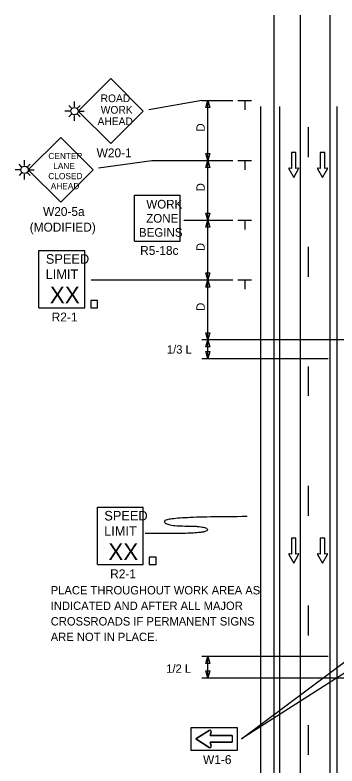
# Model space of a CAD drawing. Extents: x 16748 to 18475, y 7008 to 8262.
# Drawn here: x 16772 to 17041, y 7634 to 8262 of the extents above; entities that cross this region are included whole.
import ezdxf

# ---------------------------------------------------------------- set-up
doc = ezdxf.new("R2010")
doc.units = 0
for name, color, linetype in [('ALI_LEGAL_EX', 7, 'Continuous'), ('MT_SCRATCH_LEVEL_E', 7, 'Continuous'), ('PAVT_EDGE_EX', 7, 'Continuous'), ('TRAFFIC_SIGNS_PR', 7, 'Continuous'), ('TYPICAL_TEXT_DIMEN_PR', 7, 'Continuous')]:
    doc.layers.add(name, color=color, linetype=linetype)

msp = doc.modelspace()

# ---------------------------------------------------------------- linework, layer by layer
at = {"layer": 'ALI_LEGAL_EX'}
for points in [[(17017.08, 8168.47), (17017.08, 8143.47)], [(17017.08, 8068.47), (17017.08, 8043.47)], [(17017.08, 7968.47), (17017.08, 7943.81)], [(17017.08, 7868.47), (17017.08, 7843.47)], [(17017.08, 7768.47), (17017.08, 7743.47)], [(17017.08, 7668.47), (17017.08, 7643.47)]]:
    msp.add_lwpolyline(points, dxfattribs=at)
at = {"layer": 'MT_SCRATCH_LEVEL_E'}
for p, q in [((17006.75, 8147.27), (17003.01, 8147.27)), ((17003.01, 8147.27), (17003.01, 8134.01)), ((17006.75, 8147.27), (17003.01, 8147.27)), ((17003.01, 8147.27), (17003.01, 8134.01)), ((17006.75, 8134.01), (17006.75, 8147.27)), ((17006.75, 8134.01), (17006.75, 8147.27)), ((17030.82, 8147.27), (17027.08, 8147.27)), ((17027.08, 8147.27), (17027.08, 8134.01)), ((17030.82, 8147.27), (17027.08, 8147.27)), ((17027.08, 8147.27), (17027.08, 8134.01)), ((17030.82, 8134.01), (17030.82, 8147.27)), ((17030.82, 8134.01), (17030.82, 8147.27)), ((17000.75, 8133.64), (17004.9, 8126.4)), ((17000.75, 8133.64), (17004.9, 8126.4)), ((17003.01, 8134.01), (17001.23, 8134.32)), ((17003.01, 8134.01), (17001.23, 8134.32)), ((17004.9, 8126.4), (17009.01, 8133.64)), ((17004.9, 8126.4), (17009.01, 8133.64)), ((17008.53, 8134.32), (17006.75, 8134.01)), ((17008.53, 8134.32), (17006.75, 8134.01)), ((17024.82, 8133.64), (17028.97, 8126.4)), ((17024.82, 8133.64), (17028.97, 8126.4)), ((17027.08, 8134.01), (17025.3, 8134.32)), ((17027.08, 8134.01), (17025.3, 8134.32)), ((17028.97, 8126.4), (17033.08, 8133.64)), ((17028.97, 8126.4), (17033.08, 8133.64)), ((17032.6, 8134.32), (17030.82, 8134.01)), ((17032.6, 8134.32), (17030.82, 8134.01)), ((17006.75, 7824.7), (17003.01, 7824.7)), ((17003.01, 7824.7), (17003.01, 7811.45)), ((17006.75, 7824.7), (17003.01, 7824.7)), ((17003.01, 7824.7), (17003.01, 7811.45)), ((17006.75, 7811.45), (17006.75, 7824.7)), ((17006.75, 7811.45), (17006.75, 7824.7)), ((17030.82, 7824.7), (17027.08, 7824.7)), ((17027.08, 7824.7), (17027.08, 7811.45)), ((17030.82, 7824.7), (17027.08, 7824.7)), ((17027.08, 7824.7), (17027.08, 7811.45)), ((17030.82, 7811.45), (17030.82, 7824.7)), ((17030.82, 7811.45), (17030.82, 7824.7)), ((17000.75, 7811.08), (17004.9, 7803.84)), ((17000.75, 7811.08), (17004.9, 7803.84)), ((17003.01, 7811.45), (17001.23, 7811.76)), ((17003.01, 7811.45), (17001.23, 7811.76)), ((17004.9, 7803.84), (17009.01, 7811.08)), ((17004.9, 7803.84), (17009.01, 7811.08)), ((17008.53, 7811.76), (17006.75, 7811.45)), ((17008.53, 7811.76), (17006.75, 7811.45)), ((17024.82, 7811.08), (17028.97, 7803.84)), ((17024.82, 7811.08), (17028.97, 7803.84)), ((17027.08, 7811.45), (17025.3, 7811.76)), ((17027.08, 7811.45), (17025.3, 7811.76)), ((17028.97, 7803.84), (17033.08, 7811.08)), ((17028.97, 7803.84), (17033.08, 7811.08)), ((17032.6, 7811.76), (17030.82, 7811.45)), ((17032.6, 7811.76), (17030.82, 7811.45))]:
    msp.add_line(p, q, dxfattribs=at)
for centre, start, end in [((17001.16, 8133.86), 80.03619, 209.77312), ((17001.16, 8133.86), 80.03619, 209.77312), ((17008.6, 8133.86), 330.42484, 99.96381), ((17008.6, 8133.86), 330.42484, 99.96381), ((17025.23, 8133.86), 80.03619, 209.77312), ((17025.23, 8133.86), 80.03619, 209.77312), ((17032.67, 8133.86), 330.42484, 99.96381), ((17032.67, 8133.86), 330.42484, 99.96381), ((17001.16, 7811.3), 80.03619, 209.77312), ((17001.16, 7811.3), 80.03619, 209.77312), ((17008.6, 7811.3), 330.42484, 99.96381), ((17008.6, 7811.3), 330.42484, 99.96381), ((17025.23, 7811.3), 80.03619, 209.77312), ((17025.23, 7811.3), 80.03619, 209.77312), ((17032.67, 7811.3), 330.42484, 99.96381), ((17032.67, 7811.3), 330.42484, 99.96381)]:
    msp.add_arc(centre, 0.463, start, end, dxfattribs=at)
at = {"layer": 'PAVT_EDGE_EX'}
for p, q in [((16988.15, 8262.34), (16988.15, 7433.15)), ((17010.15, 8262.34), (17010.15, 7433.15)), ((17035.15, 8262.34), (17035.15, 7433.15)), ((16977.08, 8185.96), (16977.08, 7352.54)), ((16993.08, 8185.96), (16993.08, 7352.54)), ((17041.08, 8185.96), (17041.08, 7352.54))]:
    msp.add_line(p, q, dxfattribs=at)
at = {"layer": 'TRAFFIC_SIGNS_PR'}
for p, q in [((16851.77, 8209.12), (16824.59, 8181.93)), ((16878.96, 8181.93), (16851.77, 8209.12)), ((16818.92, 8184.45), (16816.81, 8186.55)), ((16821.43, 8185.49), (16821.43, 8189.99)), ((16823.95, 8184.45), (16826.06, 8186.55)), ((16818.28, 8181.93), (16813.44, 8181.93)), ((16818.92, 8179.42), (16816.81, 8177.31)), ((16821.43, 8173.97), (16821.43, 8178.38)), ((16823.95, 8179.42), (16826.05, 8177.31)), ((16824.59, 8181.93), (16851.77, 8154.75)), ((16824.59, 8181.93), (16829.47, 8181.93)), ((16851.77, 8154.75), (16878.96, 8181.93)), ((16809.95, 8160), (16782.8, 8132.84)), ((16837.1, 8132.84), (16809.95, 8160)), ((16779.65, 8136.4), (16779.65, 8140.9)), ((16777.13, 8135.36), (16775.02, 8137.46)), ((16782.16, 8135.36), (16784.27, 8137.46)), ((16776.49, 8132.84), (16771.65, 8132.84)), ((16777.13, 8130.33), (16775.02, 8128.22)), ((16779.65, 8124.88), (16779.65, 8129.29)), ((16782.16, 8130.33), (16784.27, 8128.22)), ((16782.8, 8132.84), (16787.68, 8132.84)), ((16782.8, 8132.84), (16809.95, 8105.69)), ((16809.95, 8105.69), (16837.1, 8132.84)), ((16871.56, 8073.15), (16871.56, 8111.55)), ((16871.56, 8111.55), (16909.96, 8111.55)), ((16909.96, 8073.15), (16909.96, 8111.55)), ((16871.56, 8073.15), (16909.96, 8073.15)), ((16791.69, 8065.45), (16830.09, 8065.45)), ((16791.69, 8017.45), (16791.69, 8065.45)), ((16830.09, 8017.45), (16830.09, 8065.45)), ((16791.69, 8017.45), (16830.09, 8017.45)), ((16840.63, 7850.72), (16879.03, 7850.72)), ((16840.63, 7802.72), (16840.63, 7850.72)), ((16879.03, 7802.72), (16879.03, 7850.72)), ((16840.63, 7802.72), (16879.03, 7802.72)), ((16934.23, 7664), (16923.07, 7656.9)), ((16935.07, 7659.7), (16935.91, 7662.76)), ((16923.07, 7656.9), (16934.23, 7649.8)), ((16953.47, 7659.7), (16935.07, 7659.7)), ((16953.47, 7659.7), (16953.47, 7654.1)), ((16935.91, 7651.04), (16935.07, 7654.1)), ((16935.07, 7654.1), (16953.47, 7654.1))]:
    msp.add_line(p, q, dxfattribs=at)
for points in [[(16835.11, 8017.45), (16840.7, 8017.45), (16840.7, 8023.62), (16835.11, 8023.62)], [(16884.04, 7802.72), (16889.64, 7802.72), (16889.64, 7808.89), (16884.04, 7808.89)], [(16957.47, 7647.3), (16919.07, 7647.3), (16919.07, 7666.5), (16957.47, 7666.5)]]:
    msp.add_lwpolyline(points, close=True, dxfattribs=at)
for points in [[(16934.23, 7649.8), (16923.07, 7656.9), (16934.23, 7664)], [(16935.91, 7662.76), (16935.07, 7659.7), (16953.47, 7659.7), (16953.47, 7654.1), (16935.07, 7654.1), (16935.91, 7651.04)]]:
    msp.add_lwpolyline(points, dxfattribs=at)
for centre in [(16821.43, 8181.93), (16779.65, 8132.84)]:
    msp.add_circle(centre, 3.15, dxfattribs=at)
for centre, start, end in [((16934.83, 7663.05), 344.67308, 122.46963), ((16934.83, 7663.05), 344.67308, 122.46962), ((16934.83, 7650.74), 237.53038, 15.32692), ((16934.83, 7650.74), 237.53038, 15.32692)]:
    msp.add_arc(centre, 1.12, start, end, dxfattribs=at)
at = {"layer": 'TYPICAL_TEXT_DIMEN_PR'}
for p, q in [((16927.98, 8190.72), (16883.54, 8183.05)), ((16927.98, 8190.72), (16953.98, 8190.72)), ((16931.41, 8184.86), (16932.98, 8190.72)), ((16932.98, 8190.72), (16934.55, 8184.86)), ((16932.98, 8140.72), (16932.98, 8190.72)), ((16958.23, 8190.72), (16969.48, 8190.72)), ((16963.86, 8190.72), (16963.86, 8182.94)), ((16932.98, 8184.86), (16931.41, 8184.86)), ((16934.55, 8184.86), (16932.98, 8184.86)), ((16932.98, 8140.72), (16931.41, 8146.59)), ((16931.41, 8146.59), (16932.98, 8146.59)), ((16932.98, 8146.59), (16934.55, 8146.59)), ((16934.55, 8146.59), (16932.98, 8140.72)), ((16841.56, 8134.45), (16886.16, 8140.72)), ((16886.16, 8140.72), (16953.98, 8140.72)), ((16931.41, 8134.86), (16932.98, 8140.72)), ((16932.98, 8140.72), (16934.55, 8134.86)), ((16932.98, 8090.72), (16932.98, 8140.72)), ((16958.23, 8140.72), (16969.48, 8140.72)), ((16963.86, 8140.72), (16963.86, 8132.94)), ((16932.98, 8134.86), (16931.41, 8134.86)), ((16934.55, 8134.86), (16932.98, 8134.86)), ((16932.98, 8090.72), (16931.41, 8096.59)), ((16931.41, 8096.59), (16932.98, 8096.59)), ((16932.98, 8096.59), (16934.55, 8096.59)), ((16934.55, 8096.59), (16932.98, 8090.72)), ((16912.93, 8090.72), (16953.98, 8090.72)), ((16931.41, 8084.86), (16932.98, 8090.72)), ((16932.98, 8090.72), (16934.55, 8084.86)), ((16932.98, 8040.72), (16932.98, 8090.72)), ((16958.23, 8090.72), (16969.48, 8090.72)), ((16963.86, 8090.72), (16963.86, 8082.94)), ((16932.98, 8084.86), (16931.41, 8084.86)), ((16934.55, 8084.86), (16932.98, 8084.86)), ((16932.98, 8040.72), (16931.41, 8046.59)), ((16931.41, 8046.59), (16932.98, 8046.59)), ((16932.98, 8046.59), (16934.55, 8046.59)), ((16934.55, 8046.59), (16932.98, 8040.72)), ((16835.45, 8040.72), (16953.98, 8040.72)), ((16931.41, 8034.86), (16932.98, 8040.72)), ((16932.98, 7990.72), (16932.98, 8040.72)), ((16932.98, 8040.72), (16934.55, 8034.86)), ((16958.23, 8040.72), (16969.48, 8040.72)), ((16963.86, 8040.72), (16963.86, 8032.94)), ((16932.98, 8034.86), (16931.41, 8034.86)), ((16934.55, 8034.86), (16932.98, 8034.86)), ((16932.98, 7990.72), (16931.41, 7996.59)), ((16931.41, 7996.59), (16932.98, 7996.59)), ((16932.98, 7996.59), (16934.55, 7996.59)), ((16934.55, 7996.59), (16932.98, 7990.72)), ((17058.17, 7990.72), (16927.98, 7990.72)), ((16931.41, 7984.86), (16932.98, 7990.72)), ((16932.98, 7974.96), (16932.98, 7990.72)), ((16932.98, 7990.72), (16934.55, 7984.86)), ((16932.98, 7984.86), (16931.41, 7984.86)), ((16934.55, 7984.86), (16932.98, 7984.86)), ((16932.98, 7974.96), (16931.41, 7980.82)), ((16931.41, 7980.82), (16932.98, 7980.82)), ((16932.98, 7980.82), (16934.55, 7980.82)), ((16934.55, 7980.82), (16932.98, 7974.96)), ((16927.98, 7974.97), (17033.61, 7974.97)), ((16927.98, 7725.97), (17033.61, 7725.97)), ((16931.41, 7720.11), (16932.98, 7725.97)), ((16932.98, 7708), (16932.98, 7725.97)), ((16932.98, 7725.97), (16934.55, 7720.11)), ((16961.04, 7656.9), (17053.42, 7725.82)), ((16932.98, 7720.11), (16931.41, 7720.11)), ((16934.55, 7720.11), (16932.98, 7720.11)), ((17061, 7720.68), (16961.04, 7656.9)), ((16932.98, 7708), (16931.41, 7713.86)), ((16931.41, 7713.86), (16932.98, 7713.86)), ((16932.98, 7713.86), (16934.55, 7713.86)), ((16934.55, 7713.86), (16932.98, 7708)), ((16927.98, 7708), (17057.62, 7708))]:
    msp.add_line(p, q, dxfattribs=at)
msp.add_open_spline([(16965.85, 7842.81), (16896.77, 7842.81), (16896.77, 7834.93), (16932.73, 7834.93), (16932.73, 7828.78), (16884.43, 7828.78), (16880.49, 7828.78)], degree=2, dxfattribs=at)

# ---------------------------------------------------------------- texts
at = {"layer": 'TRAFFIC_SIGNS_PR'}
for s, height, p in [('ROAD', 6.408, (16843.31, 8189.48)), ('WORK', 6.408, (16843.41, 8179.86)), ('AHEAD', 6.408, (16840.72, 8170.25)), ('CENTER', 5.2, (16799.53, 8141.85)), ('W20-1', 7.449, (16839.93, 8143.29)), ('LANE', 5.2, (16803.61, 8133.45)), ('CLOSED', 5.2, (16799.53, 8125.05)), ('AHEAD', 5.2, (16801.56, 8116.65)), ('WORK', 7.217, (16881.56, 8100.51)), ('W20-5a', 7.44, (16795.09, 8094.25)), ('ZONE', 7.217, (16881.44, 8088.7)), ('(MODIFIED)', 7.44, (16783.95, 8081.21)), ('BEGINS', 7.217, (16875.37, 8076.89)), ('R5-18c', 7.44, (16876.37, 8061.71)), ('SPEED', 8, (16797.46, 8054.31)), ('LIMIT', 8, (16797.3, 8041.51)), ('XX', 14.031, (16800.8, 8021.21)), ('R2-1', 7.44, (16802.37, 8006.01)), ('SPEED', 8, (16846.39, 7839.58)), ('LIMIT', 8, (16846.23, 7826.78)), ('XX', 14.031, (16849.74, 7806.47)), ('R2-1', 7.44, (16851.3, 7791.28)), ('PLACE THROUGHOUT WORK AREA AS', 7, (16801.55, 7777.75)), ('INDICATED AND AFTER ALL MAJOR', 7, (16801.55, 7764.75)), ('CROSSROADS IF PERMANENT SIGNS', 7, (16801.55, 7751.75)), ('ARE NOT IN PLACE.', 7, (16801.55, 7738.75)), ('W1-6', 7.44, (16929.01, 7635.86))]:
    msp.add_text(s, height=height, dxfattribs=at).set_placement(p)
at = {"layer": 'TYPICAL_TEXT_DIMEN_PR'}
for p in [(16930.42, 8164.94), (16930.42, 8114.94), (16930.42, 8064.94), (16930.42, 8014.94)]:
    msp.add_text('D', height=7, rotation=90, dxfattribs=at).set_placement(p)
for s, p in [('1/3 L', (16898.74, 7979.14)), ('1/2 L', (16898.18, 7712.19))]:
    msp.add_text(s, height=7, dxfattribs=at).set_placement(p)

doc.saveas('drawing.dxf')
